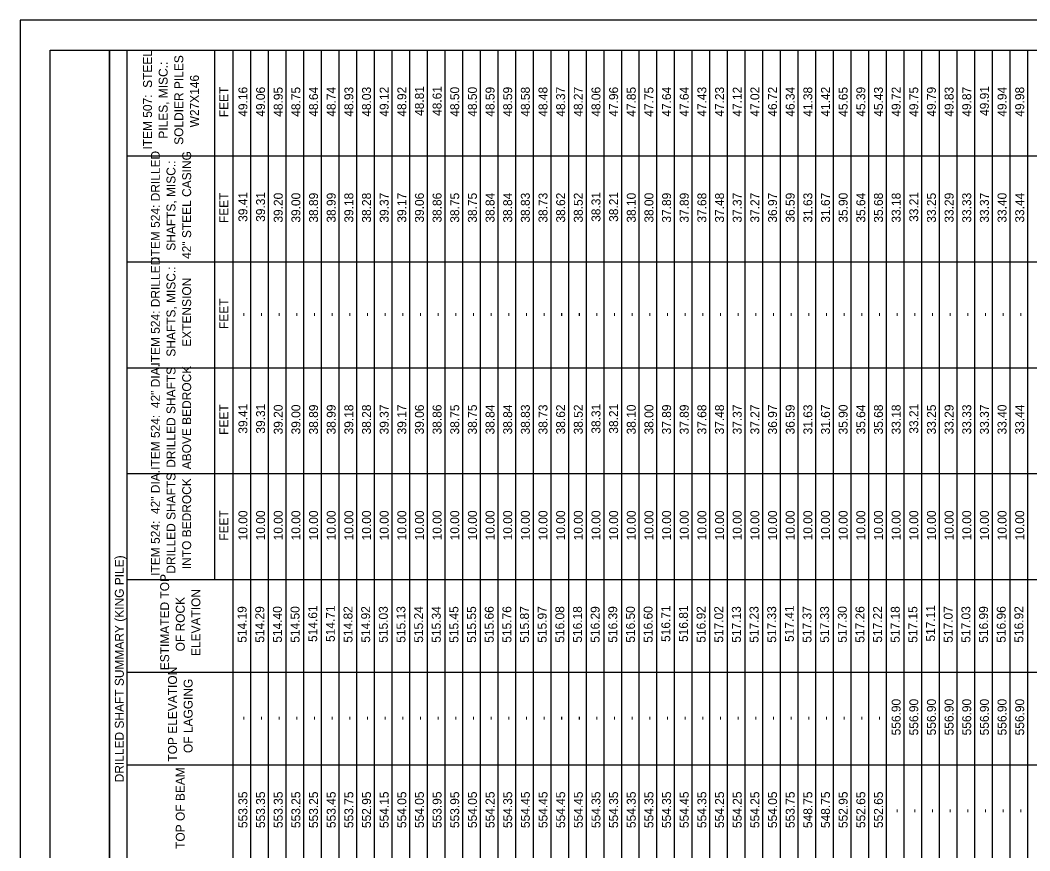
# Model space of a CAD drawing. Extents: x 0 to 34, y 0 to 22.
# Drawn here: x 0 to 16.93, y 8.07 to 22 of the extents above; entities that cross this region are included whole.
import ezdxf

# ---------------------------------------------------------------- set-up
doc = ezdxf.new("R2010")
doc.units = 0
for name, color, linetype in [('SH_Border', 7, 'Continuous'), ('SH_Cut_Line', 7, 'Continuous'), ('SH_Text', 7, 'Continuous')]:
    doc.layers.add(name, color=color, linetype=linetype)

msp = doc.modelspace()

# ---------------------------------------------------------------- linework, layer by layer
at = {"layer": 'SH_Border'}
for points in [[(0.5, 21.5), (1.5, 21.5), (1.5, 0.5), (0.5, 0.5)], [(1.5, 21.5), (33.5, 21.5), (33.5, 0.5), (1.5, 0.5)]]:
    msp.add_lwpolyline(points, close=True, dxfattribs=at)
at = {"layer": 'SH_Cut_Line'}
msp.add_lwpolyline([(0, 0), (34, 0), (34, 22), (0, 22)], close=True, dxfattribs=at)
at = {"layer": 'SH_Text'}
for p, q in [((1.5, 0.5), (1.5, 21.5)), ((1.5, 21.5), (27.28, 21.5)), ((1.796, 0.5), (1.796, 21.5)), ((3.261, 12.621), (3.261, 21.5)), ((3.572, 0.5), (3.572, 21.5)), ((3.868, 0.5), (3.868, 21.5)), ((4.164, 0.5), (4.164, 21.5)), ((4.46, 0.5), (4.46, 21.5)), ((4.756, 0.5), (4.756, 21.5)), ((5.052, 0.5), (5.052, 21.5)), ((5.348, 0.5), (5.348, 21.5)), ((5.644, 0.5), (5.644, 21.5)), ((5.94, 0.5), (5.94, 21.5)), ((6.236, 0.5), (6.236, 21.5)), ((6.532, 0.5), (6.532, 21.5)), ((6.828, 0.5), (6.828, 21.5)), ((7.124, 0.5), (7.124, 21.5)), ((7.42, 0.5), (7.42, 21.5)), ((7.716, 0.5), (7.716, 21.5)), ((8.012, 0.5), (8.012, 21.5)), ((8.308, 0.5), (8.308, 21.5)), ((8.604, 0.5), (8.604, 21.5)), ((8.9, 0.5), (8.9, 21.5)), ((9.196, 0.5), (9.196, 21.5)), ((9.492, 0.5), (9.492, 21.5)), ((9.788, 0.5), (9.788, 21.5)), ((10.084, 0.5), (10.084, 21.5)), ((10.379, 0.5), (10.379, 21.5)), ((10.675, 0.5), (10.675, 21.5)), ((10.971, 0.5), (10.971, 21.5)), ((11.267, 0.5), (11.267, 21.5)), ((11.563, 0.5), (11.563, 21.5)), ((11.859, 0.5), (11.859, 21.5)), ((12.155, 0.5), (12.155, 21.5)), ((12.451, 0.5), (12.451, 21.5)), ((12.747, 0.5), (12.747, 21.5)), ((13.043, 0.5), (13.043, 21.5)), ((13.339, 0.5), (13.339, 21.5)), ((13.635, 0.5), (13.635, 21.5)), ((13.931, 0.5), (13.931, 21.5)), ((14.227, 0.5), (14.227, 21.5)), ((14.523, 0.5), (14.523, 21.5)), ((14.819, 0.5), (14.819, 21.5)), ((15.115, 0.5), (15.115, 21.5)), ((15.411, 0.5), (15.411, 21.5)), ((15.707, 0.5), (15.707, 21.5)), ((16.003, 0.5), (16.003, 21.5)), ((16.299, 0.5), (16.299, 21.5)), ((16.595, 0.5), (16.595, 21.5)), ((16.891, 0.5), (16.891, 21.5)), ((1.796, 19.724), (27.28, 19.724)), ((1.796, 17.948), (27.28, 17.948)), ((1.796, 16.172), (27.28, 16.172)), ((1.796, 14.396), (27.28, 14.396)), ((1.796, 12.621), (3.261, 12.621)), ((3.261, 12.621), (3.572, 12.621)), ((3.572, 12.621), (27.28, 12.621)), ((1.796, 11.067), (26.969, 11.067)), ((1.796, 9.513), (26.969, 9.513))]:
    msp.add_line(p, q, dxfattribs=at)

# ---------------------------------------------------------------- texts
for s, height, p in [('ITEM 507:  STEEL ', 0.14977, (2.21, 19.83)), ('SOLDIER PILES ', 0.14977, (2.734, 19.91)), ('PILES, MISC.: ', 0.14977, (2.472, 20.013)), ('W27X146', 0.1498, (2.997, 20.203)), ('FEET', 0.1498, (3.491, 20.373)), ('49.16', 0.1498, (3.809, 20.381)), ('49.06', 0.1498, (4.105, 20.381)), ('48.95', 0.1498, (4.401, 20.38)), ('48.75', 0.1498, (4.697, 20.38)), ('48.64', 0.1498, (4.993, 20.381)), ('48.74', 0.1498, (5.289, 20.381)), ('48.93', 0.1498, (5.585, 20.381)), ('48.03', 0.1498, (5.881, 20.381)), ('49.12', 0.1498, (6.177, 20.382)), ('48.92', 0.1498, (6.473, 20.382)), ('48.81', 0.1498, (6.768, 20.394)), ('48.61', 0.1498, (7.064, 20.394)), ('48.50', 0.1498, (7.36, 20.381)), ('48.50', 0.1498, (7.656, 20.381)), ('48.59', 0.1498, (7.952, 20.381)), ('48.59', 0.1498, (8.248, 20.381)), ('48.58', 0.1498, (8.544, 20.381)), ('48.48', 0.1498, (8.84, 20.381)), ('48.37', 0.1498, (9.136, 20.381)), ('48.27', 0.1498, (9.432, 20.381)), ('48.06', 0.1498, (9.728, 20.381)), ('47.96', 0.1498, (10.024, 20.381)), ('47.85', 0.1498, (10.32, 20.38)), ('47.75', 0.1498, (10.616, 20.38)), ('47.64', 0.1498, (10.912, 20.381)), ('47.64', 0.1498, (11.208, 20.381)), ('47.43', 0.1498, (11.504, 20.381)), ('47.23', 0.1498, (11.8, 20.381)), ('47.12', 0.1498, (12.096, 20.382)), ('47.02', 0.1498, (12.392, 20.382)), ('46.72', 0.1498, (12.688, 20.382)), ('46.34', 0.1498, (12.984, 20.381)), ('41.38', 0.1498, (13.28, 20.381)), ('41.42', 0.1498, (13.576, 20.382)), ('45.65', 0.1498, (13.872, 20.38)), ('45.39', 0.1498, (14.168, 20.381)), ('45.43', 0.1498, (14.464, 20.381)), ('49.72', 0.1498, (14.76, 20.382)), ('49.75', 0.1498, (15.056, 20.38)), ('49.79', 0.1498, (15.352, 20.381)), ('49.83', 0.1498, (15.648, 20.381)), ('49.87', 0.1498, (15.944, 20.381)), ('49.91', 0.1498, (16.24, 20.394)), ('49.94', 0.1498, (16.536, 20.381)), ('49.98', 0.1498, (16.832, 20.381)), ('ITEM 524: DRILLED ', 0.14977, (2.341, 17.983)), ('42" STEEL CASING', 0.14977, (2.866, 17.996)), ('SHAFTS, MISC.: ', 0.14977, (2.603, 18.133)), ('FEET', 0.1498, (3.491, 18.597)), ('39.41', 0.1498, (3.809, 18.618)), ('39.31', 0.1498, (4.105, 18.618)), ('39.20', 0.1498, (4.401, 18.605)), ('39.00', 0.1498, (4.697, 18.605)), ('38.89', 0.1498, (4.993, 18.605)), ('38.99', 0.1498, (5.289, 18.605)), ('39.18', 0.1498, (5.585, 18.605)), ('38.28', 0.1498, (5.881, 18.605)), ('39.37', 0.1498, (6.177, 18.605)), ('39.17', 0.1498, (6.473, 18.605)), ('39.06', 0.1498, (6.768, 18.605)), ('38.86', 0.1498, (7.064, 18.605)), ('38.75', 0.1498, (7.36, 18.604)), ('38.75', 0.1498, (7.656, 18.604)), ('38.84', 0.1498, (7.952, 18.605)), ('38.84', 0.1498, (8.248, 18.605)), ('38.83', 0.1498, (8.544, 18.605)), ('38.73', 0.1498, (8.84, 18.605)), ('38.62', 0.1498, (9.136, 18.606)), ('38.52', 0.1498, (9.432, 18.606)), ('38.31', 0.1498, (9.728, 18.618)), ('38.21', 0.1498, (10.024, 18.618)), ('38.10', 0.1498, (10.32, 18.605)), ('38.00', 0.1498, (10.616, 18.605)), ('37.89', 0.1498, (10.912, 18.605)), ('37.89', 0.1498, (11.208, 18.605)), ('37.68', 0.1498, (11.504, 18.605)), ('37.48', 0.1498, (11.8, 18.605)), ('37.37', 0.1498, (12.096, 18.605)), ('37.27', 0.1498, (12.392, 18.605)), ('36.97', 0.1498, (12.688, 18.605)), ('36.59', 0.1498, (12.984, 18.605)), ('31.63', 0.1498, (13.28, 18.605)), ('31.67', 0.1498, (13.576, 18.605)), ('35.90', 0.1498, (13.872, 18.605)), ('35.64', 0.1498, (14.168, 18.605)), ('35.68', 0.1498, (14.464, 18.605)), ('33.18', 0.1498, (14.76, 18.605)), ('33.21', 0.1498, (15.056, 18.618)), ('33.25', 0.1498, (15.352, 18.604)), ('33.29', 0.1498, (15.648, 18.605)), ('33.33', 0.1498, (15.944, 18.605)), ('33.37', 0.1498, (16.24, 18.605)), ('33.40', 0.1498, (16.536, 18.605)), ('33.44', 0.1498, (16.832, 18.605)), ('ITEM 524: DRILLED ', 0.14977, (2.341, 16.207)), ('SHAFTS, MISC.: ', 0.14977, (2.603, 16.357)), ('EXTENSION', 0.1498, (2.866, 16.524)), ('FEET', 0.1498, (3.491, 16.821)), ('-', 0.15, (3.809, 17.032)), ('-', 0.15, (4.105, 17.032)), ('-', 0.15, (4.401, 17.032)), ('-', 0.15, (4.697, 17.032)), ('-', 0.15, (4.993, 17.032)), ('-', 0.15, (5.289, 17.032)), ('-', 0.15, (5.585, 17.032)), ('-', 0.15, (5.881, 17.032)), ('-', 0.15, (6.177, 17.032)), ('-', 0.15, (6.473, 17.032)), ('-', 0.15, (6.768, 17.032)), ('-', 0.15, (7.064, 17.032)), ('-', 0.15, (7.36, 17.032)), ('-', 0.15, (7.656, 17.032)), ('-', 0.15, (7.952, 17.032)), ('-', 0.15, (8.248, 17.032)), ('-', 0.15, (8.544, 17.032)), ('-', 0.15, (8.84, 17.032)), ('-', 0.15, (9.136, 17.032)), ('-', 0.15, (9.432, 17.032)), ('-', 0.15, (9.728, 17.032)), ('-', 0.15, (10.024, 17.032)), ('-', 0.15, (10.32, 17.032)), ('-', 0.15, (10.616, 17.032)), ('-', 0.15, (10.912, 17.032)), ('-', 0.15, (11.208, 17.032)), ('-', 0.15, (11.504, 17.032)), ('-', 0.15, (11.8, 17.032)), ('-', 0.15, (12.096, 17.032)), ('-', 0.15, (12.392, 17.032)), ('-', 0.15, (12.688, 17.032)), ('-', 0.15, (12.984, 17.032)), ('-', 0.15, (13.28, 17.032)), ('-', 0.15, (13.576, 17.032)), ('-', 0.15, (13.872, 17.032)), ('-', 0.15, (14.168, 17.032)), ('-', 0.15, (14.464, 17.032)), ('-', 0.15, (14.76, 17.032)), ('-', 0.15, (15.056, 17.032)), ('-', 0.15, (15.352, 17.032)), ('-', 0.15, (15.648, 17.032)), ('-', 0.15, (15.944, 17.032)), ('-', 0.15, (16.24, 17.032)), ('-', 0.15, (16.536, 17.032)), ('-', 0.15, (16.832, 17.032)), ('ITEM 524:  42" DIA. ', 0.14977, (2.341, 14.459)), ('DRILLED SHAFTS ', 0.14977, (2.603, 14.494)), ('ABOVE BEDROCK', 0.14977, (2.866, 14.468)), ('FEET', 0.1498, (3.491, 15.046)), ('39.41', 0.1498, (3.809, 15.066)), ('39.31', 0.1498, (4.105, 15.066)), ('39.20', 0.1498, (4.401, 15.053)), ('39.00', 0.1498, (4.697, 15.053)), ('38.89', 0.1498, (4.993, 15.053)), ('38.99', 0.1498, (5.289, 15.053)), ('39.18', 0.1498, (5.585, 15.053)), ('38.28', 0.1498, (5.881, 15.053)), ('39.37', 0.1498, (6.177, 15.053)), ('39.17', 0.1498, (6.473, 15.053)), ('39.06', 0.1498, (6.768, 15.053)), ('38.86', 0.1498, (7.064, 15.053)), ('38.75', 0.1498, (7.36, 15.053)), ('38.75', 0.1498, (7.656, 15.053)), ('38.84', 0.1498, (7.952, 15.053)), ('38.84', 0.1498, (8.248, 15.053)), ('38.83', 0.1498, (8.544, 15.053)), ('38.73', 0.1498, (8.84, 15.053)), ('38.62', 0.1498, (9.136, 15.054)), ('38.52', 0.1498, (9.432, 15.054)), ('38.31', 0.1498, (9.728, 15.066)), ('38.21', 0.1498, (10.024, 15.066)), ('38.10', 0.1498, (10.32, 15.053)), ('38.00', 0.1498, (10.616, 15.053)), ('37.89', 0.1498, (10.912, 15.053)), ('37.89', 0.1498, (11.208, 15.053)), ('37.68', 0.1498, (11.504, 15.053)), ('37.48', 0.1498, (11.8, 15.053)), ('37.37', 0.1498, (12.096, 15.053)), ('37.27', 0.1498, (12.392, 15.053)), ('36.97', 0.1498, (12.688, 15.053)), ('36.59', 0.1498, (12.984, 15.053)), ('31.63', 0.1498, (13.28, 15.053)), ('31.67', 0.1498, (13.576, 15.053)), ('35.90', 0.1498, (13.872, 15.053)), ('35.64', 0.1498, (14.168, 15.053)), ('35.68', 0.1498, (14.464, 15.053)), ('33.18', 0.1498, (14.76, 15.053)), ('33.21', 0.1498, (15.056, 15.066)), ('33.25', 0.1498, (15.352, 15.053)), ('33.29', 0.1498, (15.648, 15.053)), ('33.33', 0.1498, (15.944, 15.053)), ('33.37', 0.1498, (16.24, 15.053)), ('33.40', 0.1498, (16.536, 15.053)), ('33.44', 0.1498, (16.832, 15.053)), ('ITEM 524:  42" DIA. ', 0.14977, (2.341, 12.683)), ('DRILLED SHAFTS ', 0.14977, (2.603, 12.718)), ('INTO BEDROCK', 0.14977, (2.866, 12.794)), ('FEET', 0.1498, (3.491, 13.27)), ('10.00', 0.1498, (3.809, 13.277)), ('10.00', 0.1498, (4.105, 13.277)), ('10.00', 0.1498, (4.401, 13.277)), ('10.00', 0.1498, (4.697, 13.277)), ('10.00', 0.1498, (4.993, 13.277)), ('10.00', 0.1498, (5.289, 13.277)), ('10.00', 0.1498, (5.585, 13.277)), ('10.00', 0.1498, (5.881, 13.277)), ('10.00', 0.1498, (6.177, 13.277)), ('10.00', 0.1498, (6.473, 13.277)), ('10.00', 0.1498, (6.768, 13.277)), ('10.00', 0.1498, (7.064, 13.277)), ('10.00', 0.1498, (7.36, 13.277)), ('10.00', 0.1498, (7.656, 13.277)), ('10.00', 0.1498, (7.952, 13.277)), ('10.00', 0.1498, (8.248, 13.277)), ('10.00', 0.1498, (8.544, 13.277)), ('10.00', 0.1498, (8.84, 13.277)), ('10.00', 0.1498, (9.136, 13.277)), ('10.00', 0.1498, (9.432, 13.277)), ('10.00', 0.1498, (9.728, 13.277)), ('10.00', 0.1498, (10.024, 13.277)), ('10.00', 0.1498, (10.32, 13.277)), ('10.00', 0.1498, (10.616, 13.277)), ('10.00', 0.1498, (10.912, 13.277)), ('10.00', 0.1498, (11.208, 13.277)), ('10.00', 0.1498, (11.504, 13.277)), ('10.00', 0.1498, (11.8, 13.277)), ('10.00', 0.1498, (12.096, 13.277)), ('10.00', 0.1498, (12.392, 13.277)), ('10.00', 0.1498, (12.688, 13.277)), ('10.00', 0.1498, (12.984, 13.277)), ('10.00', 0.1498, (13.28, 13.277)), ('10.00', 0.1498, (13.576, 13.277)), ('10.00', 0.1498, (13.872, 13.277)), ('10.00', 0.1498, (14.168, 13.277)), ('10.00', 0.1498, (14.464, 13.277)), ('10.00', 0.1498, (14.76, 13.277)), ('10.00', 0.1498, (15.056, 13.277)), ('10.00', 0.1498, (15.352, 13.277)), ('10.00', 0.1498, (15.648, 13.277)), ('10.00', 0.1498, (15.944, 13.277)), ('10.00', 0.1498, (16.24, 13.277)), ('10.00', 0.1498, (16.536, 13.277)), ('10.00', 0.1498, (16.832, 13.277)), ('DRILLED SHAFT SUMMARY (KING PILE)', 0.14977, (1.737, 9.219)), ('ESTIMATED TOP ', 0.14977, (2.497, 11.099)), ('ELEVATION', 0.1498, (3.021, 11.337)), ('OF ROCK ', 0.1498, (2.759, 11.415)), ('514.19', 0.1498, (3.795, 11.56)), ('514.29', 0.1498, (4.091, 11.56)), ('514.40', 0.1498, (4.387, 11.56)), ('514.50', 0.1498, (4.683, 11.56)), ('514.61', 0.1498, (4.979, 11.573)), ('514.71', 0.1498, (5.275, 11.573)), ('514.82', 0.1498, (5.571, 11.561)), ('514.92', 0.1498, (5.867, 11.561)), ('515.03', 0.1498, (6.163, 11.56)), ('515.13', 0.1498, (6.459, 11.56)), ('515.24', 0.1498, (6.755, 11.56)), ('515.34', 0.1498, (7.051, 11.56)), ('515.45', 0.1498, (7.347, 11.559)), ('515.55', 0.1498, (7.643, 11.559)), ('515.66', 0.1498, (7.939, 11.56)), ('515.76', 0.1498, (8.235, 11.56)), ('515.87', 0.1498, (8.53, 11.56)), ('515.97', 0.1498, (8.826, 11.56)), ('516.08', 0.1498, (9.122, 11.56)), ('516.18', 0.1498, (9.418, 11.56)), ('516.29', 0.1498, (9.714, 11.56)), ('516.39', 0.1498, (10.01, 11.56)), ('516.50', 0.1498, (10.306, 11.56)), ('516.60', 0.1498, (10.602, 11.56)), ('516.71', 0.1498, (10.898, 11.573)), ('516.81', 0.1498, (11.194, 11.573)), ('516.92', 0.1498, (11.49, 11.561)), ('517.02', 0.1498, (11.786, 11.561)), ('517.13', 0.1498, (12.082, 11.56)), ('517.23', 0.1498, (12.378, 11.56)), ('517.33', 0.1498, (12.674, 11.56)), ('517.41', 0.1498, (12.97, 11.573)), ('517.37', 0.1498, (13.266, 11.56)), ('517.33', 0.1498, (13.562, 11.56)), ('517.30', 0.1498, (13.858, 11.56)), ('517.26', 0.1498, (14.154, 11.56)), ('517.22', 0.1498, (14.45, 11.561)), ('517.18', 0.1498, (14.746, 11.56)), ('517.15', 0.1498, (15.042, 11.559)), ('517.11', 0.1498, (15.338, 11.58)), ('517.07', 0.1498, (15.634, 11.56)), ('517.03', 0.1498, (15.93, 11.56)), ('516.99', 0.1498, (16.226, 11.56)), ('516.96', 0.1498, (16.522, 11.56)), ('516.92', 0.1498, (16.818, 11.561)), ('TOP ELEVATION ', 0.14977, (2.628, 9.566)), ('OF LAGGING', 0.1498, (2.89, 9.71)), ('556.90', 0.1498, (14.76, 10.006)), ('556.90', 0.1498, (15.056, 10.006)), ('556.90', 0.1498, (15.352, 10.006)), ('556.90', 0.1498, (15.648, 10.006)), ('556.90', 0.1498, (15.944, 10.006)), ('556.90', 0.1498, (16.24, 10.006)), ('556.90', 0.1498, (16.536, 10.006)), ('556.90', 0.1498, (16.832, 10.006)), ('-', 0.15, (3.809, 10.261)), ('-', 0.15, (4.105, 10.261)), ('-', 0.15, (4.401, 10.261)), ('-', 0.15, (4.697, 10.261)), ('-', 0.15, (4.993, 10.261)), ('-', 0.15, (5.289, 10.261)), ('-', 0.15, (5.585, 10.261)), ('-', 0.15, (5.881, 10.261)), ('-', 0.15, (6.177, 10.261)), ('-', 0.15, (6.473, 10.261)), ('-', 0.15, (6.768, 10.261)), ('-', 0.15, (7.064, 10.261)), ('-', 0.15, (7.36, 10.261)), ('-', 0.15, (7.656, 10.261)), ('-', 0.15, (7.952, 10.261)), ('-', 0.15, (8.248, 10.261)), ('-', 0.15, (8.544, 10.261)), ('-', 0.15, (8.84, 10.261)), ('-', 0.15, (9.136, 10.261)), ('-', 0.15, (9.432, 10.261)), ('-', 0.15, (9.728, 10.261)), ('-', 0.15, (10.024, 10.261)), ('-', 0.15, (10.32, 10.261)), ('-', 0.15, (10.616, 10.261)), ('-', 0.15, (10.912, 10.261)), ('-', 0.15, (11.208, 10.261)), ('-', 0.15, (11.504, 10.261)), ('-', 0.15, (11.8, 10.261)), ('-', 0.15, (12.096, 10.261)), ('-', 0.15, (12.392, 10.261)), ('-', 0.15, (12.688, 10.261)), ('-', 0.15, (12.984, 10.261)), ('-', 0.15, (13.28, 10.261)), ('-', 0.15, (13.576, 10.261)), ('-', 0.15, (13.872, 10.261)), ('-', 0.15, (14.168, 10.261)), ('-', 0.15, (14.464, 10.261)), ('TOP OF BEAM', 0.14977, (2.759, 8.103)), ('553.35', 0.1498, (3.809, 8.452)), ('553.35', 0.1498, (4.105, 8.452)), ('553.35', 0.1498, (4.401, 8.452)), ('553.25', 0.1498, (4.697, 8.452)), ('553.25', 0.1498, (4.993, 8.452)), ('553.45', 0.1498, (5.289, 8.452)), ('553.75', 0.1498, (5.585, 8.452)), ('552.95', 0.1498, (5.881, 8.452)), ('554.15', 0.1498, (6.177, 8.452)), ('554.05', 0.1498, (6.473, 8.452)), ('554.05', 0.1498, (6.768, 8.452)), ('553.95', 0.1498, (7.064, 8.452)), ('553.95', 0.1498, (7.36, 8.452)), ('554.05', 0.1498, (7.656, 8.452)), ('554.25', 0.1498, (7.952, 8.452)), ('554.35', 0.1498, (8.248, 8.452)), ('554.45', 0.1498, (8.544, 8.452)), ('554.45', 0.1498, (8.84, 8.452)), ('554.45', 0.1498, (9.136, 8.452)), ('554.45', 0.1498, (9.432, 8.452)), ('554.35', 0.1498, (9.728, 8.452)), ('554.35', 0.1498, (10.024, 8.452)), ('554.35', 0.1498, (10.32, 8.452)), ('554.35', 0.1498, (10.616, 8.452)), ('554.35', 0.1498, (10.912, 8.452)), ('554.45', 0.1498, (11.208, 8.452)), ('554.35', 0.1498, (11.504, 8.452)), ('554.25', 0.1498, (11.8, 8.452)), ('554.25', 0.1498, (12.096, 8.452)), ('554.25', 0.1498, (12.392, 8.452)), ('554.05', 0.1498, (12.688, 8.452)), ('553.75', 0.1498, (12.984, 8.452)), ('548.75', 0.1498, (13.28, 8.452)), ('548.75', 0.1498, (13.576, 8.452)), ('552.95', 0.1498, (13.872, 8.452)), ('552.65', 0.1498, (14.168, 8.452)), ('552.65', 0.1498, (14.464, 8.452)), ('-', 0.15, (14.76, 8.707)), ('-', 0.15, (15.056, 8.707)), ('-', 0.15, (15.352, 8.707)), ('-', 0.15, (15.648, 8.707)), ('-', 0.15, (15.944, 8.707)), ('-', 0.15, (16.24, 8.707)), ('-', 0.15, (16.536, 8.707)), ('-', 0.15, (16.832, 8.707))]:
    msp.add_text(s, height=height, rotation=90, dxfattribs=at).set_placement(p)

doc.saveas('drawing.dxf')
